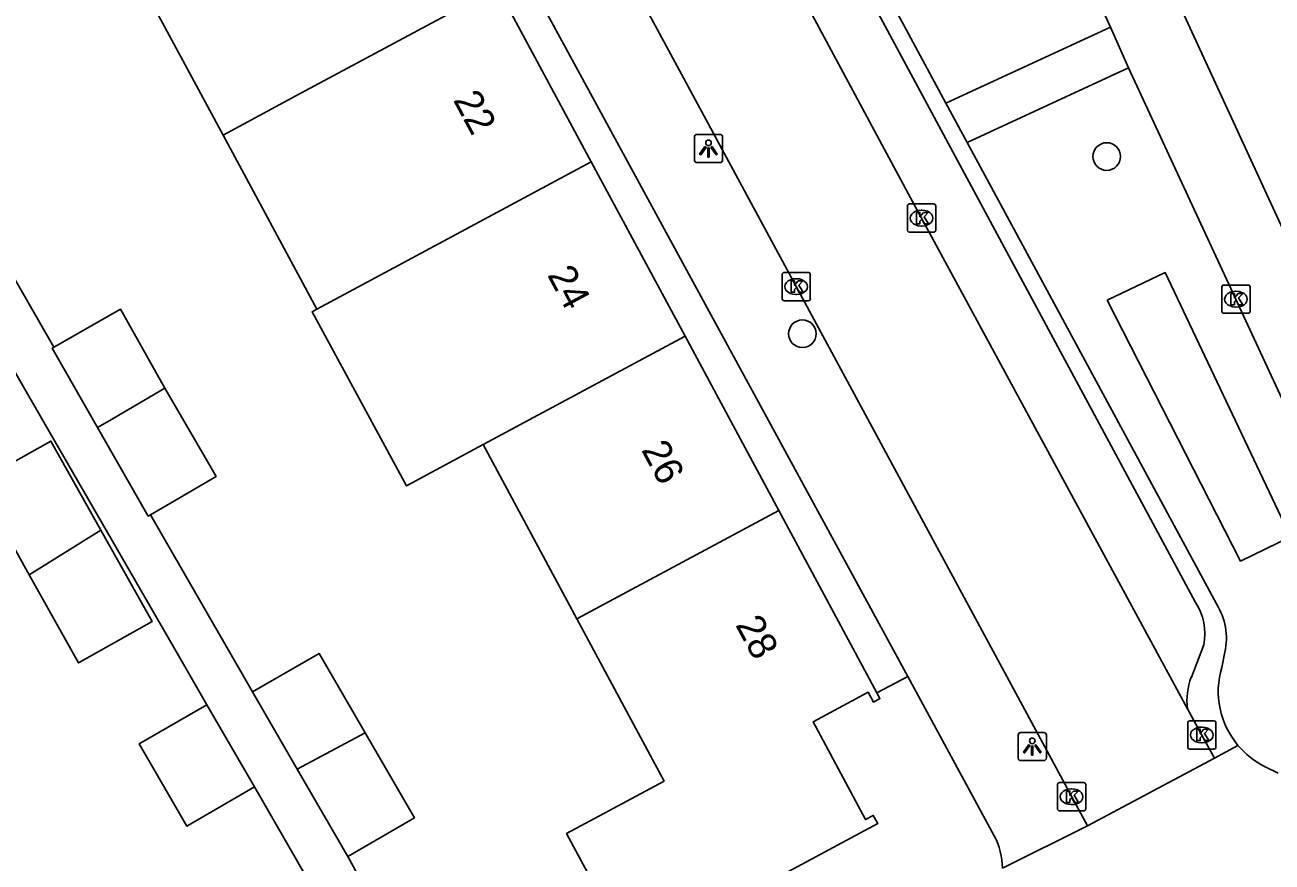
# Model space of a CAD drawing. Extents: x 162532 to 163264, y 381233 to 382042.
# Drawn here: x 162761.54 to 162805.65, y 381807.38 to 381836.99 of the extents above; entities that cross this region are included whole.
import ezdxf

# ---------------------------------------------------------------- set-up
doc = ezdxf.new("R2010")
doc.units = 0
for name, color, linetype in [('IMGEO_Boom', 7, 'Continuous'), ('IMGEO_Erf', 7, 'Continuous'), ('IMGEO_Groenvoorziening', 7, 'Continuous'), ('IMGEO_Kolk', 7, 'Continuous'), ('IMGEO_Lichtpunt', 7, 'Continuous'), ('IMGEO_Pand', 7, 'Continuous'), ('IMGEO_Pand_nummerreeks', 7, 'Continuous'), ('IMGEO_Rijbaan_lokaal_open', 7, 'Continuous'), ('IMGEO_Voetpad_open', 7, 'Continuous')]:
    doc.layers.add(name, color=color, linetype=linetype)

msp = doc.modelspace()

# ---------------------------------------------------------------- linework, layer by layer
at = {"layer": 'IMGEO_Boom'}
for centre in [(162799.803, 381832.332), (162789.04, 381826.064)]:
    msp.add_circle(centre, 0.489, dxfattribs=at)
at = {"layer": 'IMGEO_Erf'}
msp.add_lwpolyline([(162792.763, 381813.94), (162791.67, 381813.368)], dxfattribs=at)
at = {"layer": 'IMGEO_Groenvoorziening'}
msp.add_lwpolyline([(162799.822, 381827.253), (162801.868, 381828.226), (162806.302, 381818.885), (162804.536, 381818.026), (162799.822, 381827.253)], dxfattribs=at)
at = {"layer": 'IMGEO_Kolk'}
for p, q in [((162792.753, 381829.728), (162792.753, 381830.58)), ((162792.828, 381830.654), (162793.68, 381830.654)), ((162793.241, 381830.434), (162793.266, 381830.434)), ((162793.754, 381830.58), (162793.754, 381829.728)), ((162793.68, 381829.654), (162792.828, 381829.654)), ((162793.264, 381829.874), (162793.239, 381829.874)), ((162788.318, 381827.306), (162788.318, 381828.158)), ((162788.393, 381828.232), (162789.245, 381828.232)), ((162789.319, 381828.158), (162789.319, 381827.306)), ((162788.806, 381828.012), (162788.831, 381828.012)), ((162803.872, 381826.862), (162803.872, 381827.714)), ((162803.947, 381827.788), (162804.799, 381827.788)), ((162804.873, 381827.714), (162804.873, 381826.862)), ((162788.829, 381827.452), (162788.804, 381827.452)), ((162804.36, 381827.568), (162804.385, 381827.568)), ((162789.245, 381827.232), (162788.393, 381827.232)), ((162804.383, 381827.008), (162804.358, 381827.008)), ((162804.799, 381826.788), (162803.947, 381826.788)), ((162802.665, 381811.448), (162802.665, 381812.3)), ((162802.74, 381812.374), (162803.592, 381812.374)), ((162803.666, 381812.3), (162803.666, 381811.448)), ((162803.153, 381812.154), (162803.178, 381812.154)), ((162803.592, 381811.374), (162802.74, 381811.374)), ((162803.176, 381811.594), (162803.151, 381811.594)), ((162798.057, 381809.265), (162798.057, 381810.117)), ((162798.132, 381810.191), (162798.984, 381810.191)), ((162799.058, 381810.117), (162799.058, 381809.265)), ((162798.545, 381809.971), (162798.57, 381809.971)), ((162798.984, 381809.191), (162798.132, 381809.191)), ((162798.568, 381809.411), (162798.543, 381809.411))]:
    msp.add_line(p, q, dxfattribs=at)
for points in [[(162792.753, 381829.728), (162792.753, 381830.58)], [(162792.828, 381830.654), (162793.68, 381830.654)], [(162793.074, 381830.354), (162793.197, 381830.354), (162793.197, 381830.203), (162793.327, 381830.354), (162793.491, 381830.354), (162793.345, 381830.203), (162793.498, 381829.954), (162793.346, 381829.954), (162793.261, 381830.118), (162793.197, 381830.051), (162793.197, 381829.954), (162793.074, 381829.954), (162793.074, 381830.354)], [(162793.754, 381830.58), (162793.754, 381829.728)], [(162793.68, 381829.654), (162792.828, 381829.654)], [(162788.318, 381827.306), (162788.318, 381828.158)], [(162788.393, 381828.232), (162789.245, 381828.232)], [(162789.319, 381828.158), (162789.319, 381827.306)], [(162788.639, 381827.932), (162788.762, 381827.932), (162788.762, 381827.781), (162788.892, 381827.932), (162789.056, 381827.932), (162788.91, 381827.781), (162789.063, 381827.532), (162788.911, 381827.532), (162788.826, 381827.696), (162788.762, 381827.629), (162788.762, 381827.532), (162788.639, 381827.532), (162788.639, 381827.932)], [(162803.872, 381826.862), (162803.872, 381827.714)], [(162803.947, 381827.788), (162804.799, 381827.788)], [(162804.873, 381827.714), (162804.873, 381826.862)], [(162804.193, 381827.488), (162804.316, 381827.488), (162804.316, 381827.337), (162804.446, 381827.488), (162804.61, 381827.488), (162804.464, 381827.337), (162804.617, 381827.088), (162804.465, 381827.088), (162804.38, 381827.252), (162804.316, 381827.185), (162804.316, 381827.088), (162804.193, 381827.088), (162804.193, 381827.488)], [(162789.245, 381827.232), (162788.393, 381827.232)], [(162804.799, 381826.788), (162803.947, 381826.788)], [(162802.665, 381811.448), (162802.665, 381812.3)], [(162802.74, 381812.374), (162803.592, 381812.374)], [(162803.666, 381812.3), (162803.666, 381811.448)], [(162802.986, 381812.074), (162803.109, 381812.074), (162803.109, 381811.923), (162803.239, 381812.074), (162803.403, 381812.074), (162803.257, 381811.923), (162803.41, 381811.674), (162803.258, 381811.674), (162803.173, 381811.838), (162803.109, 381811.771), (162803.109, 381811.674), (162802.986, 381811.674), (162802.986, 381812.074)], [(162803.592, 381811.374), (162802.74, 381811.374)], [(162798.057, 381809.265), (162798.057, 381810.117)], [(162798.132, 381810.191), (162798.984, 381810.191)], [(162799.058, 381810.117), (162799.058, 381809.265)], [(162798.378, 381809.891), (162798.501, 381809.891), (162798.501, 381809.74), (162798.631, 381809.891), (162798.795, 381809.891), (162798.649, 381809.74), (162798.802, 381809.491), (162798.65, 381809.491), (162798.565, 381809.655), (162798.501, 381809.588), (162798.501, 381809.491), (162798.378, 381809.491), (162798.378, 381809.891)], [(162798.984, 381809.191), (162798.132, 381809.191)]]:
    msp.add_lwpolyline(points, dxfattribs=at)
for centre, start, end in [((162792.83, 381830.578), 91.552, 178.448), ((162792.83, 381830.578), 91.552, 178.448), ((162793.678, 381830.578), 1.552, 88.448), ((162793.678, 381830.578), 1.552, 88.448), ((162792.83, 381829.73), 181.552, 268.448), ((162792.83, 381829.73), 181.552, 268.448), ((162793.678, 381829.73), 271.552, 358.448), ((162793.678, 381829.73), 271.552, 358.448), ((162788.395, 381828.156), 91.552, 178.448), ((162788.395, 381828.156), 91.552, 178.448), ((162789.243, 381828.156), 1.552, 88.448), ((162789.243, 381828.156), 1.552, 88.448), ((162803.949, 381827.712), 91.552, 178.448), ((162803.949, 381827.712), 91.552, 178.448), ((162804.797, 381827.712), 1.552, 88.448), ((162804.797, 381827.712), 1.552, 88.448), ((162788.395, 381827.308), 181.552, 268.448), ((162788.395, 381827.308), 181.552, 268.448), ((162789.243, 381827.308), 271.552, 358.448), ((162789.243, 381827.308), 271.552, 358.448), ((162803.949, 381826.864), 181.552, 268.448), ((162803.949, 381826.864), 181.552, 268.448), ((162804.797, 381826.864), 271.552, 358.448), ((162804.797, 381826.864), 271.552, 358.448), ((162802.742, 381812.298), 91.552, 178.448), ((162802.742, 381812.298), 91.552, 178.448), ((162803.59, 381812.298), 1.552, 88.448), ((162803.59, 381812.298), 1.552, 88.448), ((162802.742, 381811.45), 181.552, 268.448), ((162802.742, 381811.45), 181.552, 268.448), ((162803.59, 381811.45), 271.552, 358.448), ((162803.59, 381811.45), 271.552, 358.448), ((162798.134, 381810.115), 91.552, 178.448), ((162798.134, 381810.115), 91.552, 178.448), ((162798.982, 381810.115), 1.552, 88.448), ((162798.982, 381810.115), 1.552, 88.448), ((162798.134, 381809.267), 181.552, 268.448), ((162798.134, 381809.267), 181.552, 268.448), ((162798.982, 381809.267), 271.552, 358.448), ((162798.982, 381809.267), 271.552, 358.448)]:
    msp.add_arc(centre, 0.0765, start, end, dxfattribs=at)
for centre, major_axis, ratio, start_param, end_param in [((162793.24, 381830.154), (-0.387, 0.002), 0.722429, 4.712389, 7.853982), ((162793.265, 381830.154), (-0.39, 0.002), 0.717154, 1.570796, 4.712389), ((162788.805, 381827.732), (-0.387, 0.002), 0.722429, 4.712389, 7.853982), ((162788.83, 381827.732), (-0.39, 0.002), 0.717154, 1.570796, 4.712389), ((162804.359, 381827.288), (-0.387, 0.002), 0.722429, 4.712389, 7.853982), ((162804.384, 381827.288), (-0.39, 0.002), 0.717154, 1.570796, 4.712389), ((162803.152, 381811.874), (-0.387, 0.002), 0.722429, 4.712389, 7.853982), ((162803.177, 381811.874), (-0.39, 0.002), 0.717154, 1.570796, 4.712389), ((162798.544, 381809.691), (-0.387, 0.002), 0.722429, 4.712389, 7.853982), ((162798.569, 381809.691), (-0.39, 0.002), 0.717154, 1.570796, 4.712389)]:
    msp.add_ellipse(centre, major_axis=major_axis, ratio=ratio, start_param=start_param, end_param=end_param, dxfattribs=at)
at = {"layer": 'IMGEO_Lichtpunt'}
for p, q in [((162785.218, 381833.019), (162785.218, 381832.212)), ((162785.218, 381833.019), (162785.218, 381832.212)), ((162786.12, 381833.114), (162785.312, 381833.114)), ((162786.12, 381833.114), (162785.312, 381833.114)), ((162786.214, 381832.212), (162786.214, 381833.019)), ((162786.214, 381832.212), (162786.214, 381833.019)), ((162785.312, 381832.118), (162786.12, 381832.118)), ((162785.312, 381832.118), (162786.12, 381832.118)), ((162796.67, 381811.868), (162796.67, 381811.061)), ((162796.67, 381811.868), (162796.67, 381811.061)), ((162797.572, 381811.963), (162796.764, 381811.963)), ((162797.572, 381811.963), (162796.764, 381811.963)), ((162797.666, 381811.061), (162797.666, 381811.868)), ((162797.666, 381811.061), (162797.666, 381811.868)), ((162796.764, 381810.967), (162797.572, 381810.967)), ((162796.764, 381810.967), (162797.572, 381810.967))]:
    msp.add_line(p, q, dxfattribs=at)
for points in [[(162785.592, 381832.683), (162785.631, 381832.655), (162785.443, 381832.393), (162785.405, 381832.42), (162785.592, 381832.683)], [(162785.694, 381832.635), (162785.741, 381832.635), (162785.741, 381832.313), (162785.694, 381832.313), (162785.694, 381832.635)], [(162785.804, 381832.655), (162785.842, 381832.682), (162786.029, 381832.42), (162785.99, 381832.392), (162785.804, 381832.655)], [(162797.044, 381811.532), (162797.083, 381811.504), (162796.895, 381811.242), (162796.857, 381811.269), (162797.044, 381811.532)], [(162797.146, 381811.484), (162797.193, 381811.484), (162797.193, 381811.162), (162797.146, 381811.162), (162797.146, 381811.484)], [(162797.256, 381811.504), (162797.294, 381811.531), (162797.481, 381811.269), (162797.442, 381811.241), (162797.256, 381811.504)]]:
    msp.add_lwpolyline(points, dxfattribs=at)
for centre in [(162785.717, 381832.817), (162797.169, 381811.666)]:
    msp.add_circle(centre, 0.0994, dxfattribs=at)
for centre, start, end in [((162785.312, 381833.019), 90, 180), ((162785.312, 381833.019), 90, 180), ((162786.12, 381833.019), 0, 90), ((162786.12, 381833.019), 0, 90), ((162785.312, 381832.212), 180, 270), ((162785.312, 381832.212), 180, 270), ((162786.12, 381832.212), 270, 0), ((162786.12, 381832.212), 270, 360), ((162796.764, 381811.868), 90, 180), ((162796.764, 381811.868), 90, 180), ((162797.572, 381811.868), 0, 90), ((162797.572, 381811.868), 0, 90), ((162796.764, 381811.061), 180, 270), ((162796.764, 381811.061), 180, 270), ((162797.572, 381811.061), 270, 0), ((162797.572, 381811.061), 270, 360)]:
    msp.add_arc(centre, 0.0946, start, end, dxfattribs=at)
at = {"layer": 'IMGEO_Pand'}
for points in [[(162767.802, 381840.64), (162765.232, 381839.258), (162768.548, 381833.093)], [(162768.548, 381833.093), (162771.118, 381834.475), (162778.257, 381838.311)], [(162781.572, 381832.146), (162778.257, 381838.311)], [(162771.863, 381826.929), (162768.548, 381833.093)], [(162781.572, 381832.146), (162774.433, 381828.31), (162771.863, 381826.929)], [(162784.887, 381825.982), (162781.572, 381832.146)], [(162766.485, 381824.134), (162764.916, 381826.933), (162762.668, 381825.648), (162762.568, 381825.59)], [(162771.863, 381826.929), (162771.698, 381826.84), (162775.034, 381820.686), (162777.748, 381822.145)], [(162777.748, 381822.145), (162784.887, 381825.982)], [(162788.202, 381819.816), (162784.887, 381825.982)], [(162762.568, 381825.59), (162762.505, 381825.554), (162764.11, 381822.751)], [(162766.485, 381824.134), (162764.458, 381822.954), (162764.273, 381822.846), (162764.11, 381822.751)], [(162765.98, 381819.663), (162768.301, 381821.021), (162768.002, 381821.543), (162766.485, 381824.134)], [(162764.11, 381822.751), (162765.904, 381819.618), (162765.98, 381819.663)], [(162761.694, 381817.541), (162759.86, 381820.813), (162762.458, 381822.27), (162764.226, 381819.117)], [(162781.063, 381815.98), (162777.748, 381822.145)], [(162788.202, 381819.816), (162781.063, 381815.98)], [(162791.67, 381813.368), (162788.202, 381819.816)], [(162761.694, 381817.541), (162763.441, 381814.425), (162766.04, 381815.882), (162764.226, 381819.117)], [(162764.226, 381819.117), (162761.694, 381817.541)], [(162791.67, 381813.368), (162791.781, 381813.161), (162791.549, 381813.036), (162791.362, 381813.383), (162789.415, 381812.336), (162791.272, 381808.884), (162791.546, 381809.031), (162791.702, 381808.74), (162783.018, 381804.07), (162780.697, 381808.385), (162784.149, 381810.242), (162781.063, 381815.98)], [(162769.587, 381813.396), (162771.944, 381814.761), (162773.569, 381811.953)], [(162771.169, 381810.663), (162769.587, 381813.396)], [(162767.975, 381812.942), (162765.58, 381811.556), (162767.262, 381808.65), (162769.657, 381810.036)], [(162767.975, 381812.942), (162769.657, 381810.036)], [(162773.569, 381811.953), (162771.169, 381810.663)], [(162773.569, 381811.953), (162775.314, 381808.939), (162772.957, 381807.575)], [(162772.957, 381807.575), (162771.169, 381810.663)]]:
    msp.add_lwpolyline(points, dxfattribs=at)
at = {"layer": 'IMGEO_Rijbaan_lokaal_open'}
for points in [[(162799.119, 381808.655), (162784.611, 381835.53), (162772.767, 381857.443), (162768.958, 381864.708), (162759.427, 381882.237), (162750.943, 381898.002), (162749.572, 381900.789), (162749.263, 381901.449)], [(162802.661, 381812.802), (162792.865, 381830.868), (162784.378, 381846.682), (162778.787, 381857.004), (162770.784, 381871.85), (162762.713, 381886.779), (162756.718, 381898.098), (162755.199, 381901.032)], [(162802.661, 381812.802), (162803.17, 381811.863), (162803.612, 381811.049)], [(162803.612, 381811.049), (162799.119, 381808.655)]]:
    msp.add_lwpolyline(points, dxfattribs=at)
at = {"layer": 'IMGEO_Voetpad_open'}
for points in [[(162813.9, 381812.685), (162767.041, 381914.342)], [(162746.054, 381900.628), (162777.492, 381842.022), (162792.763, 381813.94)], [(162758.099, 381899.571), (162775.404, 381867.717), (162802.933, 381816.582)], [(162789.094, 381860.53), (162799.932, 381836.912)], [(162794.115, 381834.218), (162781.865, 381856.968)], [(162799.932, 381836.912), (162794.115, 381834.218)], [(162799.932, 381836.912), (162800.57, 381835.472)], [(162800.57, 381835.472), (162794.87, 381832.83)], [(162800.57, 381835.472), (162810.522, 381814.015)], [(162794.87, 381832.83), (162794.115, 381834.218)], [(162803.684, 381816.507), (162794.87, 381832.83)], [(162759.052, 381831.7), (162762.568, 381825.59)], [(162759.129, 381828.269), (162761.902, 381823.466), (162767.323, 381814.077), (162767.975, 381812.942)], [(162765.98, 381819.663), (162769.587, 381813.396)], [(162803.234, 381815.058), (162802.795, 381813.919)], [(162803.87, 381814.264), (162803.978, 381814.803)], [(162792.763, 381813.94), (162795.826, 381808.308)], [(162804.443, 381811.506), (162803.612, 381811.049)], [(162805.869, 381810.523), (162805.386, 381810.762)], [(162769.657, 381810.036), (162772.186, 381805.655), (162774.478, 381798.601)], [(162799.119, 381808.655), (162796.115, 381807.158)], [(162772.957, 381807.575), (162773.831, 381805.989), (162775.038, 381802.563), (162776.456, 381799.2)]]:
    msp.add_lwpolyline(points, dxfattribs=at)
for centre, radius, start, end in [((162801.256, 381815.459), 2.019, 348.5415, 33.8035), ((162801.768, 381815.299), 2.265, 347.3538, 32.2245), ((162806.716, 381813.417), 2.97, 163.4231, 220.0504), ((162804.885, 381813.102), 2.245, 158.6459, 187.6726), ((162806.73, 381813.435), 2.991, 220.1452, 243.3099), ((162793.484, 381807.108), 2.631, 1.084, 27.1291)]:
    msp.add_arc(centre, radius, start, end, dxfattribs=at)

# ---------------------------------------------------------------- texts
at = {"layer": 'IMGEO_Pand_nummerreeks'}
for s, rotation, p in [('22', 298.2695, (162776.671, 381834.333)), ('24', 298.2695, (162779.999, 381828.145)), ('26', 298.2688, (162783.325, 381821.96)), ('28', 298.2688, (162786.652, 381815.772))]:
    msp.add_text(s, height=1, rotation=rotation, dxfattribs=at).set_placement(p)

doc.saveas('drawing.dxf')
